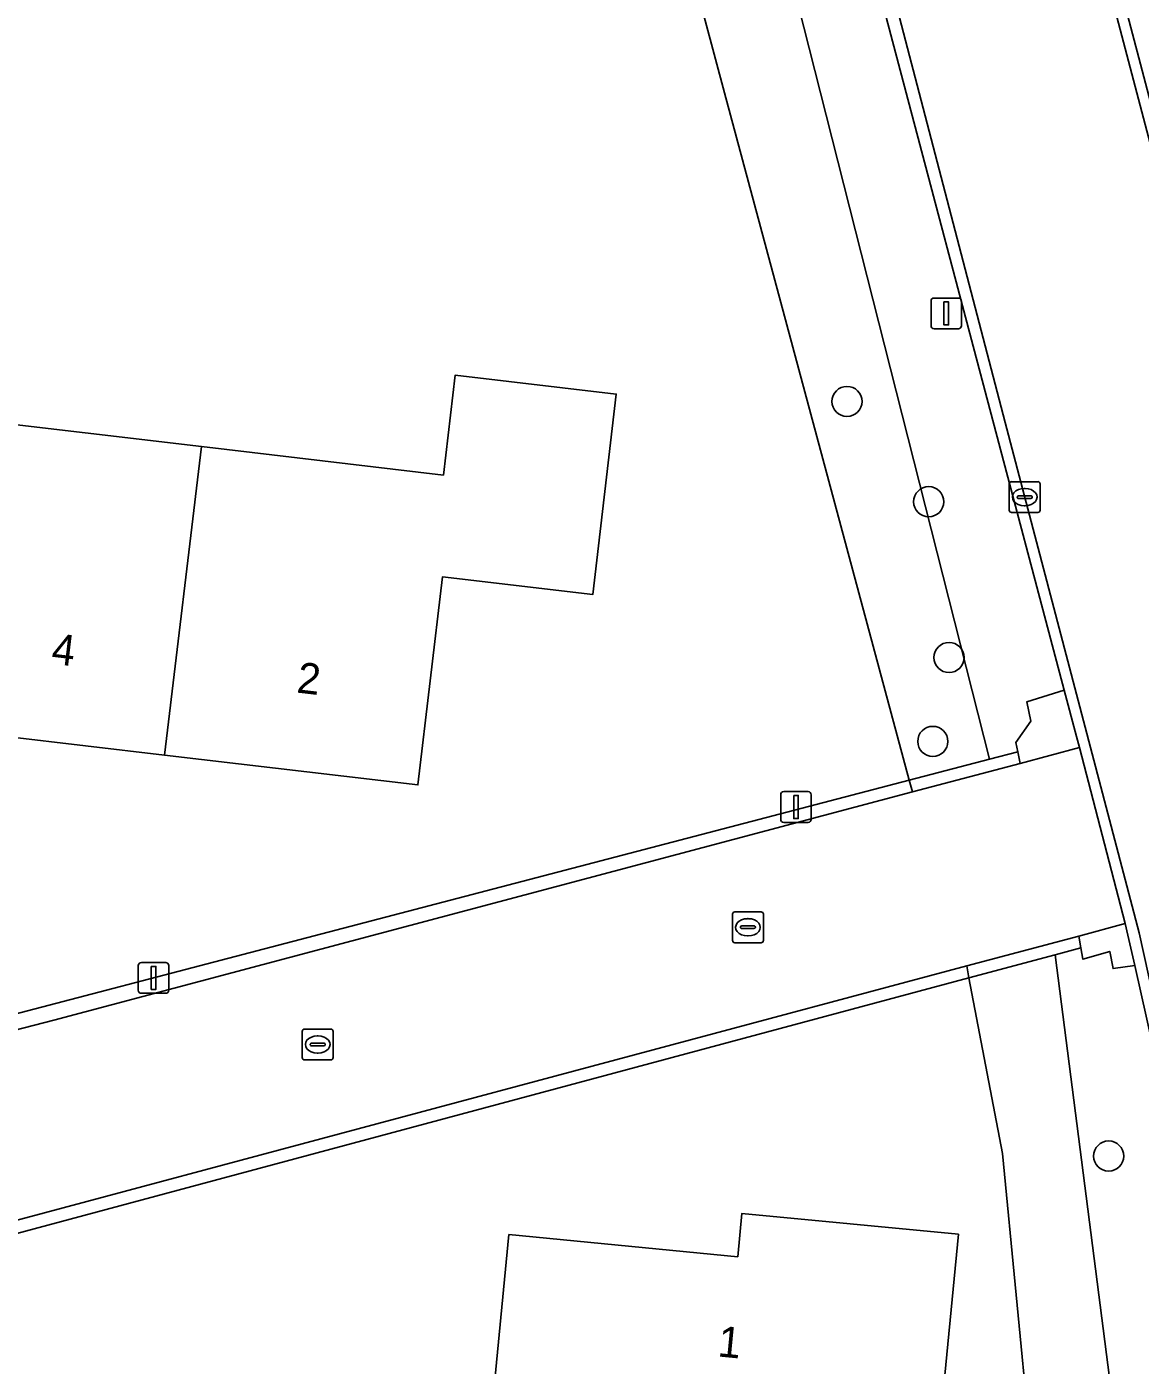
# Model space of a CAD drawing. Extents: x 162156 to 163172, y 378995 to 380779.
# Drawn here: x 162638.89 to 162675.04, y 380458.71 to 380502.14 of the extents above; entities that cross this region are included whole.
import ezdxf

# ---------------------------------------------------------------- set-up
doc = ezdxf.new("R2010")
doc.units = 0
for name, color, linetype in [('IMGEO_Boom', 7, 'Continuous'), ('IMGEO_Erf', 7, 'Continuous'), ('IMGEO_Groenvoorziening', 7, 'Continuous'), ('IMGEO_Kolk', 7, 'Continuous'), ('IMGEO_Lichtmast', 7, 'Continuous'), ('IMGEO_Pand', 7, 'Continuous'), ('IMGEO_Pand_nummerreeks', 7, 'Continuous'), ('IMGEO_Rijbaan_lokaal_gesloten', 7, 'Continuous'), ('IMGEO_Rijbaan_lokaal_open', 7, 'Continuous'), ('IMGEO_Voetpad_open', 7, 'Continuous')]:
    doc.layers.add(name, color=color, linetype=linetype)

msp = doc.modelspace()

# ---------------------------------------------------------------- linework, layer by layer
at = {"layer": 'IMGEO_Boom'}
for centre in [(162665.521, 380489.983), (162668.174, 380486.729), (162668.834, 380481.673), (162668.307, 380478.95), (162674.016, 380465.494)]:
    msp.add_circle(centre, 0.489, dxfattribs=at)
at = {"layer": 'IMGEO_Erf'}
for points in [[(162600.793, 380472.961), (162603.123, 380471.871), (162611.699, 380463.642), (162616.565, 380464.361), (162667.543, 380477.694), (162661.54, 380500), (162651.656, 380537.009)], [(162637.004, 380489.406), (162644.561, 380488.518), (162652.421, 380487.595), (162652.802, 380490.838), (162658.031, 380490.223), (162657.266, 380483.715), (162652.386, 380484.288), (162651.593, 380477.536), (162643.366, 380478.503), (162635.66, 380479.408)]]:
    msp.add_lwpolyline(points, dxfattribs=at)
for points in [[(162670.571, 380465.579), (162669.481, 380471.274), (162620.024, 380458.009), (162613.427, 380456.794), (162617.964, 380424.039), (162634.993, 380422.187), (162672.345, 380447.227)], [(162653.72, 380454.411), (162654.545, 380462.943), (162661.976, 380462.224), (162662.112, 380463.634), (162669.14, 380462.954), (162668.352, 380454.81), (162664.85, 380455.148), (162664.677, 380453.351)]]:
    msp.add_lwpolyline(points, close=True, dxfattribs=at)
at = {"layer": 'IMGEO_Groenvoorziening'}
for points in [[(162660.655, 380525.668), (162657.416, 380538.596), (162655.034, 380537.94), (162664.661, 380500), (162670.147, 380478.375), (162671.065, 380478.615), (162671.005, 380478.911), (162671.486, 380479.608), (162671.361, 380480.235), (162672.577, 380480.608), (162667.446, 380500)], [(162670.147, 380478.375), (162664.661, 380500), (162655.034, 380537.94), (162651.656, 380537.009), (162661.54, 380500), (162667.543, 380477.694)], [(162672.345, 380447.227), (162672.73, 380443.999), (162675.637, 380445.897), (162675.255, 380448.864), (162672.276, 380472.024), (162669.481, 380471.274), (162670.571, 380465.579)], [(162676.968, 380459.923), (162676.036, 380466.449), (162674.862, 380471.673), (162674.16, 380471.577), (162674.05, 380472.137), (162673.181, 380471.883), (162673.118, 380472.25), (162672.276, 380472.024), (162675.255, 380448.864), (162675.637, 380445.897), (162678.198, 380447.57), (162677.92, 380450.363)]]:
    msp.add_lwpolyline(points, close=True, dxfattribs=at)
at = {"layer": 'IMGEO_Kolk'}
for p, q in [((162670.79, 380486.453), (162670.79, 380487.305)), ((162670.865, 380487.379), (162671.717, 380487.379)), ((162671.791, 380487.305), (162671.791, 380486.453)), ((162671.049, 380486.873), (162671.049, 380486.885)), ((162671.487, 380486.836), (162671.089, 380486.836)), ((162671.092, 380486.922), (162671.49, 380486.922)), ((162671.278, 380487.159), (162671.303, 380487.159)), ((162671.533, 380486.885), (162671.533, 380486.873)), ((162671.717, 380486.379), (162670.865, 380486.379)), ((162671.301, 380486.599), (162671.276, 380486.599)), ((162661.805, 380472.492), (162661.805, 380473.344)), ((162661.88, 380473.418), (162662.732, 380473.418)), ((162662.806, 380473.344), (162662.806, 380472.492)), ((162662.064, 380472.912), (162662.064, 380472.924)), ((162662.502, 380472.875), (162662.104, 380472.875)), ((162662.107, 380472.961), (162662.505, 380472.961)), ((162662.293, 380473.198), (162662.318, 380473.198)), ((162662.548, 380472.924), (162662.548, 380472.912)), ((162662.732, 380472.418), (162661.88, 380472.418)), ((162662.316, 380472.638), (162662.291, 380472.638)), ((162647.837, 380468.688), (162647.837, 380469.54)), ((162647.912, 380469.614), (162648.764, 380469.614)), ((162648.325, 380469.394), (162648.35, 380469.394)), ((162648.838, 380469.54), (162648.838, 380468.688)), ((162648.096, 380469.108), (162648.096, 380469.12)), ((162648.534, 380469.071), (162648.136, 380469.071)), ((162648.139, 380469.157), (162648.537, 380469.157)), ((162648.58, 380469.12), (162648.58, 380469.108)), ((162648.764, 380468.614), (162647.912, 380468.614)), ((162648.348, 380468.834), (162648.323, 380468.834))]:
    msp.add_line(p, q, dxfattribs=at)
for points in [[(162670.79, 380486.453), (162670.79, 380487.305)], [(162670.865, 380487.379), (162671.717, 380487.379)], [(162671.791, 380487.305), (162671.791, 380486.453)], [(162671.717, 380486.379), (162670.865, 380486.379)], [(162661.805, 380472.492), (162661.805, 380473.344)], [(162661.88, 380473.418), (162662.732, 380473.418)], [(162662.806, 380473.344), (162662.806, 380472.492)], [(162662.732, 380472.418), (162661.88, 380472.418)], [(162647.837, 380468.688), (162647.837, 380469.54)], [(162647.912, 380469.614), (162648.764, 380469.614)], [(162648.838, 380469.54), (162648.838, 380468.688)], [(162648.764, 380468.614), (162647.912, 380468.614)]]:
    msp.add_lwpolyline(points, dxfattribs=at)
for centre, radius, start, end in [((162670.867, 380487.303), 0.0765, 91.552, 178.448), ((162670.867, 380487.303), 0.0765, 91.552, 178.448), ((162671.715, 380487.303), 0.0765, 1.552, 88.448), ((162671.715, 380487.303), 0.0765, 1.552, 88.448), ((162671.089, 380486.882), 0.0403, 85.8775, 175.7526), ((162671.086, 380486.872), 0.0366, 178.938, 274.7102), ((162671.49, 380486.879), 0.043, 264.8664, 352.4533), ((162671.494, 380486.884), 0.0386, 1.7309, 96.639), ((162670.867, 380486.455), 0.0765, 181.552, 268.448), ((162670.867, 380486.455), 0.0765, 181.552, 268.448), ((162671.715, 380486.455), 0.0765, 271.552, 358.448), ((162671.715, 380486.455), 0.0765, 271.552, 358.448), ((162661.882, 380473.342), 0.0765, 91.552, 178.448), ((162661.882, 380473.342), 0.0765, 91.552, 178.448), ((162662.73, 380473.342), 0.0765, 1.552, 88.448), ((162662.73, 380473.342), 0.0765, 1.552, 88.448), ((162662.104, 380472.921), 0.0403, 85.8775, 175.7526), ((162662.101, 380472.911), 0.0366, 178.938, 274.7102), ((162662.505, 380472.918), 0.043, 264.8664, 352.4533), ((162662.509, 380472.923), 0.0386, 1.7309, 96.639), ((162661.882, 380472.494), 0.0765, 181.552, 268.448), ((162661.882, 380472.494), 0.0765, 181.552, 268.448), ((162662.73, 380472.494), 0.0765, 271.552, 358.448), ((162662.73, 380472.494), 0.0765, 271.552, 358.448), ((162647.914, 380469.538), 0.0765, 91.552, 178.448), ((162647.914, 380469.538), 0.0765, 91.552, 178.448), ((162648.762, 380469.538), 0.0765, 1.552, 88.448), ((162648.762, 380469.538), 0.0765, 1.552, 88.448), ((162648.136, 380469.117), 0.0403, 85.8775, 175.7526), ((162648.133, 380469.107), 0.0366, 178.938, 274.7102), ((162648.537, 380469.114), 0.043, 264.8664, 352.4533), ((162648.541, 380469.119), 0.0386, 1.7309, 96.639), ((162647.914, 380468.69), 0.0765, 181.552, 268.448), ((162647.914, 380468.69), 0.0765, 181.552, 268.448), ((162648.762, 380468.69), 0.0765, 271.552, 358.448), ((162648.762, 380468.69), 0.0765, 271.552, 358.448)]:
    msp.add_arc(centre, radius, start, end, dxfattribs=at)
for centre, major_axis, ratio, start_param, end_param in [((162671.277, 380486.879), (-0.387, 0.002), 0.722429, 4.712389, 7.853982), ((162671.302, 380486.879), (-0.39, 0.002), 0.717154, 1.570796, 4.712389), ((162662.292, 380472.918), (-0.387, 0.002), 0.722429, 4.712389, 7.853982), ((162662.317, 380472.918), (-0.39, 0.002), 0.717154, 1.570796, 4.712389), ((162648.324, 380469.114), (-0.387, 0.002), 0.722429, 4.712389, 7.853982), ((162648.349, 380469.114), (-0.39, 0.002), 0.717154, 1.570796, 4.712389)]:
    msp.add_ellipse(centre, major_axis=major_axis, ratio=ratio, start_param=start_param, end_param=end_param, dxfattribs=at)
at = {"layer": 'IMGEO_Lichtmast'}
for p, q in [((162668.349, 380493.339), (162669.139, 380493.339)), ((162669.139, 380493.339), (162668.349, 380493.339)), ((162668.249, 380492.439), (162668.249, 380493.239)), ((162668.249, 380493.239), (162668.249, 380492.439)), ((162669.239, 380493.239), (162669.239, 380492.439)), ((162669.239, 380492.439), (162669.239, 380493.239)), ((162669.139, 380492.339), (162668.349, 380492.339)), ((162668.349, 380492.339), (162669.139, 380492.339)), ((162663.37, 380476.421), (162663.37, 380477.221)), ((162663.37, 380477.221), (162663.37, 380476.421)), ((162663.47, 380477.321), (162664.26, 380477.321)), ((162664.26, 380477.321), (162663.47, 380477.321)), ((162664.36, 380477.221), (162664.36, 380476.421)), ((162664.36, 380476.421), (162664.36, 380477.221)), ((162664.26, 380476.321), (162663.47, 380476.321)), ((162663.47, 380476.321), (162664.26, 380476.321)), ((162642.514, 380470.875), (162642.514, 380471.675)), ((162642.514, 380471.675), (162642.514, 380470.875)), ((162642.614, 380471.775), (162643.404, 380471.775)), ((162643.404, 380471.775), (162642.614, 380471.775)), ((162643.504, 380471.675), (162643.504, 380470.875)), ((162643.504, 380470.875), (162643.504, 380471.675)), ((162643.404, 380470.775), (162642.614, 380470.775)), ((162642.614, 380470.775), (162643.404, 380470.775))]:
    msp.add_line(p, q, dxfattribs=at)
for points in [[(162668.669, 380493.214), (162668.819, 380493.214), (162668.819, 380492.464), (162668.669, 380492.464), (162668.669, 380493.214)], [(162663.79, 380477.196), (162663.94, 380477.196), (162663.94, 380476.446), (162663.79, 380476.446), (162663.79, 380477.196)], [(162642.934, 380471.65), (162643.084, 380471.65), (162643.084, 380470.9), (162642.934, 380470.9), (162642.934, 380471.65)]]:
    msp.add_lwpolyline(points, dxfattribs=at)
for centre, start, end in [((162668.349, 380493.239), 90, 180), ((162668.349, 380493.239), 90, 180), ((162669.139, 380493.239), 0, 90), ((162669.139, 380493.239), 360, 90), ((162668.349, 380492.439), 180, 270), ((162668.349, 380492.439), 180, 270), ((162669.139, 380492.439), 270, 0), ((162669.139, 380492.439), 270, 0), ((162663.47, 380477.221), 90, 180), ((162663.47, 380477.221), 90, 180), ((162664.26, 380477.221), 0, 90), ((162664.26, 380477.221), 360, 90), ((162663.47, 380476.421), 180, 270), ((162663.47, 380476.421), 180, 270), ((162664.26, 380476.421), 270, 0), ((162664.26, 380476.421), 270, 0), ((162642.614, 380471.675), 90, 180), ((162642.614, 380471.675), 90, 180), ((162643.404, 380471.675), 0, 90), ((162643.404, 380471.675), 360, 90), ((162642.614, 380470.875), 180, 270), ((162642.614, 380470.875), 180, 270), ((162643.404, 380470.875), 270, 0), ((162643.404, 380470.875), 270, 0)]:
    msp.add_arc(centre, 0.1, start, end, dxfattribs=at)
at = {"layer": 'IMGEO_Pand'}
for points in [[(162644.561, 380488.518), (162637.004, 380489.406), (162637.37, 380492.522), (162632.291, 380493.118), (162632.113, 380491.599), (162631.529, 380486.633), (162631.294, 380484.379), (162631.18, 380483.304), (162636.051, 380482.732), (162635.66, 380479.408), (162643.366, 380478.503)], [(162643.366, 380478.503), (162651.593, 380477.536), (162652.386, 380484.288), (162657.266, 380483.715), (162658.031, 380490.223), (162652.802, 380490.838), (162652.421, 380487.595), (162644.561, 380488.518)], [(162664.677, 380453.351), (162664.85, 380455.148), (162668.352, 380454.81), (162669.14, 380462.954), (162662.112, 380463.634), (162661.976, 380462.224), (162654.545, 380462.943), (162653.72, 380454.411)]]:
    msp.add_lwpolyline(points, close=True, dxfattribs=at)
at = {"layer": 'IMGEO_Rijbaan_lokaal_gesloten'}
msp.add_lwpolyline([(162650.238, 380567.497), (162657.649, 380539.117), (162667.863, 380500), (162670.658, 380489.297), (162675.002, 380472.733), (162676.381, 380466.512), (162677.316, 380459.965), (162678.253, 380450.55), (162678.535, 380447.716), (162685.204, 380450.618), (162684.831, 380454.251), (162684.023, 380462.108), (162683.015, 380468.663), (162681.65, 380474.495), (162674.932, 380500), (162667.731, 380527.348), (162660.014, 380557.121), (162657.91, 380565.281)], dxfattribs=at)
msp.add_lwpolyline([(162678.253, 380450.55), (162677.316, 380459.965), (162676.381, 380466.512), (162675.002, 380472.733), (162670.658, 380489.297), (162667.863, 380500), (162657.649, 380539.117), (162657.309, 380539.028), (162657.416, 380538.596), (162660.655, 380525.668), (162667.446, 380500), (162672.577, 380480.608), (162672.973, 380479.114), (162673.069, 380478.75), (162674.555, 380473.037), (162674.64, 380472.659), (162674.862, 380471.673), (162676.036, 380466.449), (162676.968, 380459.923), (162677.92, 380450.363), (162678.198, 380447.57), (162678.535, 380447.716)], close=True, dxfattribs=at)
at = {"layer": 'IMGEO_Rijbaan_lokaal_open'}
for points in [[(162667.731, 380527.348), (162674.932, 380500), (162681.65, 380474.495), (162683.015, 380468.663), (162684.023, 380462.108), (162684.831, 380454.251), (162685.204, 380450.618), (162685.541, 380450.765), (162685.163, 380454.438), (162684.37, 380462.153), (162683.359, 380468.73), (162681.99, 380474.579), (162681.427, 380476.718), (162680.466, 380480.363), (162676.28, 380496.257), (162675.319, 380499.905), (162671.153, 380515.728)], [(162625.343, 380459.926), (162638.862, 380463.492), (162669.414, 380471.663), (162673.052, 380472.635), (162674.555, 380473.037), (162673.069, 380478.75), (162671.14, 380478.237), (162667.647, 380477.309), (162639.769, 380469.901), (162633.608, 380468.313), (162630.698, 380467.514), (162625.692, 380466.261), (162619.395, 380464.615), (162616.653, 380463.919), (162612.198, 380463.112)], [(162609.316, 380456.815), (162609.351, 380456.367), (162613.427, 380456.794), (162620.024, 380458.009), (162669.481, 380471.274), (162669.414, 380471.663), (162638.862, 380463.492), (162625.343, 380459.926), (162620.075, 380458.483)]]:
    msp.add_lwpolyline(points, dxfattribs=at)
for points in [[(162672.577, 380480.608), (162671.361, 380480.235), (162671.486, 380479.608), (162671.005, 380478.911), (162671.065, 380478.615), (162671.14, 380478.237), (162673.069, 380478.75), (162672.973, 380479.114)], [(162671.065, 380478.615), (162670.147, 380478.375), (162667.543, 380477.694), (162667.647, 380477.309), (162671.14, 380478.237)], [(162611.699, 380463.642), (162612.198, 380463.112), (162616.653, 380463.919), (162619.395, 380464.615), (162625.692, 380466.261), (162630.698, 380467.514), (162633.608, 380468.313), (162639.769, 380469.901), (162667.647, 380477.309), (162667.543, 380477.694), (162616.565, 380464.361)], [(162674.64, 380472.659), (162674.555, 380473.037), (162673.052, 380472.635), (162673.118, 380472.25), (162673.181, 380471.883), (162674.05, 380472.137), (162674.16, 380471.577), (162674.862, 380471.673)], [(162673.118, 380472.25), (162673.052, 380472.635), (162669.414, 380471.663), (162669.481, 380471.274), (162672.276, 380472.024)]]:
    msp.add_lwpolyline(points, close=True, dxfattribs=at)
at = {"layer": 'IMGEO_Voetpad_open'}
msp.add_lwpolyline([(162671.153, 380515.728), (162675.319, 380499.905), (162675.81, 380500), (162676.763, 380496.383), (162676.28, 380496.257), (162680.466, 380480.363), (162680.949, 380480.49), (162681.909, 380476.845), (162681.427, 380476.718), (162681.99, 380474.579), (162683.359, 380468.73), (162684.37, 380462.153), (162685.163, 380454.438), (162685.541, 380450.765), (162687.201, 380451.947), (162686.987, 380454.391), (162686.842, 380455.383)], dxfattribs=at)

# ---------------------------------------------------------------- texts
at = {"layer": 'IMGEO_Pand_nummerreeks'}
for s, rotation, p in [('4', 353.2964, (162639.665, 380481.474)), ('2', 353.2989, (162647.629, 380480.539)), ('1', 354.4734, (162661.298, 380458.994))]:
    msp.add_text(s, height=1, rotation=rotation, dxfattribs=at).set_placement(p)

doc.saveas('drawing.dxf')
